// Mitsubishi GX Works2 project: MC-24MR-4MT-500-FX-B例程   PLC: FX1S

PROGRAM MAIN
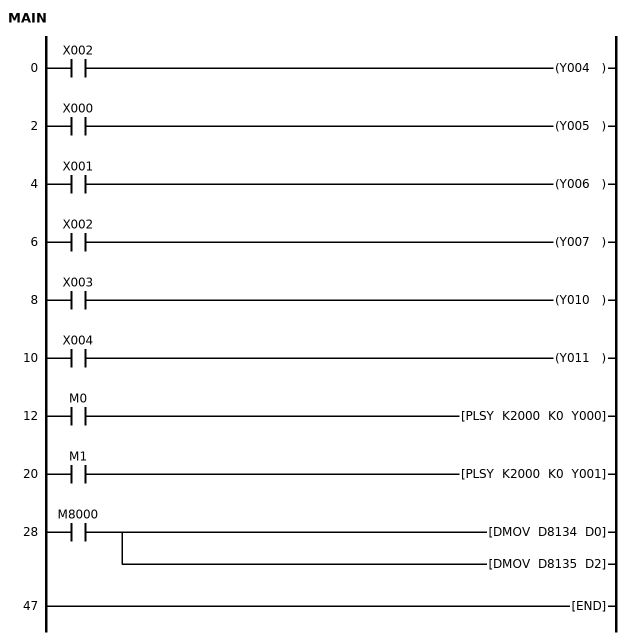
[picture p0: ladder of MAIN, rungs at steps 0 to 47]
0     LD      X002
      OUT     Y004
2     LD      X000
      OUT     Y005
4     LD      X001
      OUT     Y006
6     LD      X002
      OUT     Y007
8     LD      X003
      OUT     Y010
10    LD      X004
      OUT     Y011
12    LD      M0
      PLSY    K2000 K0 Y000
20    LD      M1
      PLSY    K2000 K0 Y001
28    LD      M8000
      DMOV    D8134 D0
      DMOV    D8135 D2
47    END
END_PROGRAM
